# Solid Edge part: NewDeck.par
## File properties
Author: morva
Template: iso metric part.par
Last saved by: morva
Revision: 104
Application: Solid Edge
Density: 2712.000 kg/m^3
Accuracy: 0.990
Username: morva
Material: Aluminum, 6061-T6
Face Style: Aluminum
Fill Style: ANSI38(Aluminum)
Virtual Style: Polished aluminum
Grouping: Metals\Aluminium Alloys
LibraryName: Materials
Coef. of Thermal Exp: 2.3e-05
Thermal Conductivity: 180.0
Specific Heat: 920.0
Modulus of Elasticity: 68947570000.0
Poisson's Ratio: 0.33
Yield Stress: 275790280.0
Ultimate Stress: 310264065.0
Elongation: 0.0
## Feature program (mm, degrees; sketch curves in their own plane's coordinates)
sketch for "unnamed RevolvedProtrusion 1" plane through (0, 0, 0) normal (0, 0, 1) x-axis (1, 0, 0)
  line (-21, 10) -> (21, 10)
  line (21, 10) -> (21, 17.5)
  line (21, 17.5) -> (32.5, 17.5)
  line (32.5, 17.5) -> (32.5, 27.5)
  line (32.5, 27.5) -> (-32.5, 27.5)
  line (-32.5, 27.5) -> (-32.5, 17.5)
  line (-32.5, 17.5) -> (-21, 17.5)
  line (-21, 17.5) -> (-21, 10)
  dimension (linear) = 32.5
  dimension (linear) = 21
  dimension (linear) = 32.5
revolve "unnamed RevolvedProtrusion 1" add full turn 360 deg
sketch for "unnamed Protrusion 1" plane through (0, 0, 0) normal (0, -1, 0) x-axis (1, 0, 0)
  line (32.5, -17.5) -> (-32.5, -17.5)
  line (-32.5, -17.5) -> (-32.5, -27.5)
  line (-32.5, -27.5) -> (237.6352, -327.2114)
  line (255, -228.7306) -> (237.6352, -327.2114)
  line (32.5, -27.5) -> (255, -228.7306)
  line (32.5, -17.5) -> (32.5, -27.5)
  dimension (linear) = 255
  dimension (linear) = 255
  dimension (linear) = 32.5
extrude "unnamed Protrusion 1" add finite 50 symmetric
sketch for "unnamed Cutout 1" plane through (0, 0, 0) normal (0, -1, 0) x-axis (1, 0, 0)
extrude "unnamed Cutout 1" cut finite 18 symmetric
sketch for "ExtrudedProtrusion_7" plane through (246.3176, 0, -277.971) normal (0.984808, 0, -0.173648) x-axis (-0.173648, 0, -0.984808)
extrude "ExtrudedProtrusion_7" add finite 50 along -normal
mirror "unnamed Mirror 1" of "ExtrudedProtrusion_7" about plane through (0, 0, 0) normal (0, -1, 0)
extrude "unnamed Protrusion 2" add finite 50
sketch for "unnamed Cutout 2" plane through (91.7467, 72, -981.8231) normal (0, 1, 0) x-axis (-0.173648, 0, -0.984808)
  line (105, 0) -> (130, 0)
  line (130, -10) -> (130, 0)
  line (105, -10) -> (130, -10)
extrude "unnamed Cutout 2" cut through along -normal
sketch for "unnamed Protrusion 3" plane through (185.5407, 0, -622.6537) normal (0.984808, 0, -0.173648) x-axis (-0.173648, 0, -0.984808)
extrude "unnamed Protrusion 3" add to key point along -normal
sketch for "unnamed Protrusion 4" plane through (110.9424, 9, -180.2232) normal (0, -1, 0) x-axis (-0.173648, 0, -0.984808)
extrude "unnamed Protrusion 4" add through along +normal
sketch for "unnamed Protrusion 5" plane through (131.6838, 0, -640.1532) normal (-0.984808, 0, 0.173648) x-axis (-0.173648, 0, -0.984808)
extrude "unnamed Protrusion 5" add finite 5 along +normal
sketch for "unnamed Protrusion 6" plane through (148.6805, 109, -658.9353) normal (0, -1, 0) x-axis (-0.173648, 0, -0.984808)
extrude "unnamed Protrusion 6" add through along +normal
sketch for "unnamed Cutout 3" plane through (185.5407, 0, -622.6537) normal (0.984808, 0, -0.173648) x-axis (-0.173648, 0, -0.984808)
extrude "unnamed Cutout 3" cut finite 20 along -normal
sketch for "Hole_13" plane through (185.5407, 0, -622.6537) normal (0.984808, 0, -0.173648) x-axis (-0.173648, 0, -0.984808)
hole "Hole_13" finite  ThreadDepth = 19 mm
sketch for "unnamed Hole 1" plane through (185.5407, 0, -622.6537) normal (0.984808, 0, -0.173648) x-axis (-0.173648, 0, -0.984808)
hole "unnamed Hole 1" finite
sketch for "unnamed Hole 2" plane through (185.5407, 0, -622.6537) normal (0.984808, 0, -0.173648) x-axis (-0.173648, 0, -0.984808)
  hole centre (-202.8405, 116) bore radius 3.3235
hole "unnamed Hole 2" finite
sketch for "unnamed Hole 3" plane through (185.5407, 0, -622.6537) normal (0.984808, 0, -0.173648) x-axis (-0.173648, 0, -0.984808)
hole "unnamed Hole 3" finite
pattern "unnamed Pattern 1" of "Hole_13", "unnamed Hole 1", "unnamed Hole 2", "unnamed Hole 3"
mirror "unnamed Mirror 2" of "unnamed Pattern 1" about plane through (0, 0, 0) normal (0, -1, 0)
hole "unnamed Hole 4" finite
hole "unnamed Hole 5" finite
hole "unnamed Hole 6" finite
hole "unnamed Hole 7" finite
sketch for "unnamed Cutout 4" plane through (185.5407, 0, -622.6537) normal (0.984808, 0, -0.173648) x-axis (-0.173648, 0, -0.984808)
extrude "unnamed Cutout 4" cut to key point along -normal
fillet "Round_15" radius 5
sketch for "Hole_25" plane through (123.7965, 0, -656.0902) normal (-0.984808, 0, 0.173648) x-axis (-0.173648, 0, -0.984808)
  hole centre (276.3497, 0) bore radius 3.3235
hole "Hole_25" nominal diameter 8 through  ThreadDepth = 50.8 mm
sketch for "unnamed Hole 8" plane through (123.7965, 0, -656.0902) normal (-0.984808, 0, 0.173648) x-axis (-0.173648, 0, -0.984808)
  hole centre (237.3497, 0) bore radius 3.3235
hole "unnamed Hole 8" through
pattern "unnamed Pattern 2" of "Hole_25", "unnamed Hole 8"
sketch for "ExtrudedCutout_28" plane through (148.7089, -125, -687.568) normal (0, -1, 0) x-axis (-0.173648, 0, -0.984808)
extrude "ExtrudedCutout_28" cut finite 14 along -normal
sketch for "unnamed Cutout 5" plane through (148.5326, -111, -688.5682) normal (0, -1, 0) x-axis (0, 0, -1)
extrude "unnamed Cutout 5" cut through along -normal
fearecompute load "unnamed FEARecomputeLoad 1"
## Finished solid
Body 1: solid body, 105 faces, 236 edges, 126 vertices.
  Faces by surface: plane 57, cylinder 40, cone 8
  Edges by curve: line 172, circle 50, ellipse 14
Bounding box of the edges (mm): 287.500 x 250.000 x 1142.558, from (-32.5, -125, -1115.0576) to (255, 125, 27.5).
Cylindrical faces by radius (mm): R3.3235 x18, R4 x1, R5 x15, R7.5 x1, R10 x2, R17.5 x2, R27.5 x1
Conical faces (half-angle, radius in mm at the cone's reference point): 59 deg R3.3235 x8
Planar faces by outward normal: +x 2, +y 6, -x 2, -y 7, -z 1, oblique 39
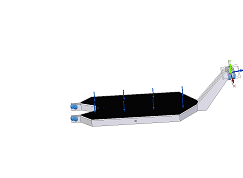
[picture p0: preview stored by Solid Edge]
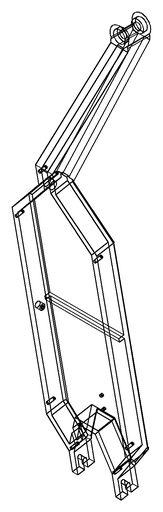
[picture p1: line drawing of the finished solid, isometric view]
